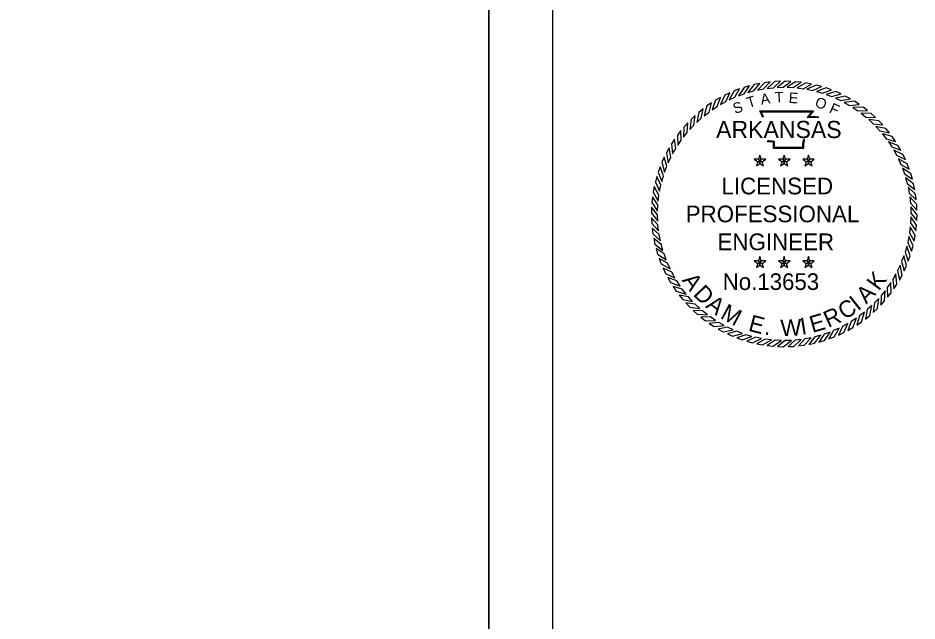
# Model space of a CAD drawing. Extents: x 759422 to 1467355, y 1662254 to 1691786.
# Drawn here: x 1466947.3 to 1467352.3, y 1691241.3 to 1691513 of the extents above; entities that cross this region are included whole.
import ezdxf

# ---------------------------------------------------------------- set-up
doc = ezdxf.new("R2010")
doc.units = 0
doc.layers.add('1', color=7, linetype='Continuous')
doc.layers.add('G-ANNO-STMP-AEW', color=7, linetype='Continuous')

msp = doc.modelspace()

# ---------------------------------------------------------------- linework, layer by layer
at = {"layer": '1'}
msp.add_line((1467159.42, 1690715.04), (1467159.42, 1691757.36), dxfattribs=at)
for points in [[(1467188.26, 1691786.2), (1465488.26, 1691786.2), (1465488.26, 1690686.2), (1467188.26, 1690686.2)], [(1465564.06, 1691229.74), (1465564.06, 1691757.36), (1466748.12, 1691757.36), (1466748.12, 1691707.96), (1466943.92, 1691707.96), (1466943.92, 1691693.36), (1467159.42, 1691693.36), (1467159.42, 1691229.74)], [(1465564.06, 1691757.36), (1466748.12, 1691757.36), (1466748.12, 1691707.96), (1466943.92, 1691707.96), (1466943.92, 1691693.36), (1467159.42, 1691693.36), (1467159.42, 1691229.74), (1465564.06, 1691229.74)]]:
    msp.add_lwpolyline(points, close=True, dxfattribs=at)
at = {"layer": 'G-ANNO-STMP-AEW'}
for points in [[(1467281.44, 1691483.49), (1467278.92, 1691482.96), (1467276.07, 1691479.37), (1467278.75, 1691480.1)], [(1467286.08, 1691484.17), (1467283.53, 1691483.84), (1467280.41, 1691480.49), (1467283.14, 1691481.01)], [(1467290.77, 1691484.49), (1467288.2, 1691484.36), (1467284.82, 1691481.27), (1467287.58, 1691481.57)], [(1467295.47, 1691484.44), (1467292.89, 1691484.51), (1467289.28, 1691481.69), (1467292.06, 1691481.78)], [(1467300.14, 1691484.02), (1467297.59, 1691484.3), (1467293.76, 1691481.77), (1467296.54, 1691481.64)], [(1467304.77, 1691483.24), (1467302.25, 1691483.71), (1467298.24, 1691481.49), (1467300.99, 1691481.14)], [(1467309.33, 1691482.09), (1467306.85, 1691482.76), (1467302.67, 1691480.86), (1467305.4, 1691480.3)], [(1467268.02, 1691479.29), (1467265.69, 1691478.18), (1467263.76, 1691474.03), (1467266.19, 1691475.37)], [(1467272.38, 1691481.04), (1467269.97, 1691480.12), (1467267.72, 1691476.13), (1467270.25, 1691477.27)], [(1467276.86, 1691482.44), (1467274.39, 1691481.72), (1467271.83, 1691477.91), (1467274.44, 1691478.86)], [(1467313.78, 1691480.59), (1467311.36, 1691481.46), (1467307.05, 1691479.89), (1467309.72, 1691479.12)], [(1467318.1, 1691478.75), (1467315.75, 1691479.8), (1467311.33, 1691478.58), (1467313.93, 1691477.6)], [(1467259.78, 1691474.79), (1467257.66, 1691473.34), (1467256.39, 1691468.93), (1467258.59, 1691470.63)], [(1467263.81, 1691477.2), (1467261.58, 1691475.92), (1467259.98, 1691471.62), (1467262.3, 1691473.15)], [(1467322.26, 1691476.57), (1467320, 1691477.81), (1467315.5, 1691476.93), (1467318.02, 1691475.75)], [(1467326.24, 1691474.08), (1467324.09, 1691475.48), (1467319.53, 1691474.96), (1467321.95, 1691473.59)], [(1467255.95, 1691472.07), (1467253.95, 1691470.45), (1467253.04, 1691465.96), (1467255.09, 1691467.83)], [(1467330.01, 1691471.28), (1467327.97, 1691472.85), (1467323.39, 1691472.69), (1467325.69, 1691471.13)], [(1467252.35, 1691469.06), (1467250.48, 1691467.29), (1467249.92, 1691462.74), (1467251.82, 1691464.77)], [(1467333.55, 1691468.19), (1467331.64, 1691469.91), (1467327.06, 1691470.11), (1467329.23, 1691468.38)], [(1467336.83, 1691464.83), (1467335.07, 1691466.7), (1467330.52, 1691467.26), (1467332.54, 1691465.36)], [(1467248.99, 1691465.77), (1467247.27, 1691463.86), (1467247.07, 1691459.28), (1467248.8, 1691461.45)], [(1467339.85, 1691461.23), (1467338.23, 1691463.23), (1467333.74, 1691464.14), (1467335.61, 1691462.09)], [(1467243.1, 1691458.46), (1467241.7, 1691456.31), (1467242.22, 1691451.75), (1467243.59, 1691454.17)], [(1467245.9, 1691462.23), (1467244.33, 1691460.19), (1467244.49, 1691455.61), (1467246.05, 1691457.91)], [(1467342.57, 1691457.4), (1467341.11, 1691459.52), (1467336.71, 1691460.79), (1467338.41, 1691458.59)], [(1467240.61, 1691454.48), (1467239.37, 1691452.23), (1467240.25, 1691447.73), (1467241.43, 1691450.24)], [(1467344.98, 1691453.37), (1467343.7, 1691455.6), (1467339.4, 1691457.2), (1467340.93, 1691454.88)], [(1467238.43, 1691450.32), (1467237.38, 1691447.97), (1467238.6, 1691443.56), (1467239.58, 1691446.16)], [(1467281.54, 1691448.52), (1467282.16, 1691449.36), (1467281.54, 1691451.25), (1467280.93, 1691449.36)], [(1467292.48, 1691448.52), (1467293.09, 1691449.36), (1467292.48, 1691451.25), (1467291.87, 1691449.36)], [(1467303.42, 1691448.52), (1467304.03, 1691449.36), (1467303.42, 1691451.25), (1467302.8, 1691449.36)], [(1467347.06, 1691449.16), (1467345.96, 1691451.49), (1467341.81, 1691453.42), (1467343.15, 1691450.99)], [(1467281.54, 1691448.52), (1467280.93, 1691449.36), (1467278.94, 1691449.36), (1467280.55, 1691448.2)], [(1467281.54, 1691448.52), (1467280.55, 1691448.2), (1467279.93, 1691446.31), (1467281.54, 1691447.47)], [(1467281.54, 1691448.52), (1467282.53, 1691448.2), (1467284.14, 1691449.36), (1467282.16, 1691449.36)], [(1467281.54, 1691448.52), (1467281.54, 1691447.47), (1467283.15, 1691446.31), (1467282.53, 1691448.2)], [(1467292.48, 1691448.52), (1467291.87, 1691449.36), (1467289.88, 1691449.36), (1467291.49, 1691448.2)], [(1467292.48, 1691448.52), (1467291.49, 1691448.2), (1467290.87, 1691446.31), (1467292.48, 1691447.47)], [(1467292.48, 1691448.52), (1467293.47, 1691448.2), (1467295.08, 1691449.36), (1467293.09, 1691449.36)], [(1467292.48, 1691448.52), (1467292.48, 1691447.47), (1467294.09, 1691446.31), (1467293.47, 1691448.2)], [(1467303.42, 1691448.52), (1467302.8, 1691449.36), (1467300.82, 1691449.36), (1467302.42, 1691448.2)], [(1467303.42, 1691448.52), (1467302.42, 1691448.2), (1467301.81, 1691446.31), (1467303.42, 1691447.47)], [(1467303.42, 1691448.52), (1467304.41, 1691448.2), (1467306.02, 1691449.36), (1467304.03, 1691449.36)], [(1467303.42, 1691448.52), (1467303.42, 1691447.47), (1467305.02, 1691446.31), (1467304.41, 1691448.2)], [(1467348.81, 1691444.8), (1467347.9, 1691447.21), (1467343.91, 1691449.46), (1467345.05, 1691446.93)], [(1467236.59, 1691446), (1467235.72, 1691443.58), (1467237.29, 1691439.27), (1467238.06, 1691441.94)], [(1467350.22, 1691440.32), (1467349.49, 1691442.79), (1467345.69, 1691445.35), (1467346.63, 1691442.74)], [(1467235.09, 1691441.55), (1467234.42, 1691439.07), (1467236.32, 1691434.9), (1467236.88, 1691437.62)], [(1467351.27, 1691435.74), (1467350.74, 1691438.26), (1467347.15, 1691441.11), (1467347.88, 1691438.43)], [(1467233.94, 1691437), (1467233.47, 1691434.47), (1467235.69, 1691430.46), (1467236.04, 1691433.22)], [(1467351.95, 1691431.1), (1467351.62, 1691433.65), (1467348.27, 1691436.77), (1467348.79, 1691434.04)], [(1467233.16, 1691432.37), (1467232.88, 1691429.81), (1467235.41, 1691425.99), (1467235.54, 1691428.76)], [(1467352.27, 1691426.41), (1467352.14, 1691428.98), (1467349.04, 1691432.36), (1467349.35, 1691429.6)], [(1467232.74, 1691427.69), (1467232.67, 1691425.12), (1467235.49, 1691421.5), (1467235.4, 1691424.28)], [(1467352.22, 1691421.71), (1467352.29, 1691424.29), (1467349.47, 1691427.9), (1467349.56, 1691425.12)], [(1467232.69, 1691422.99), (1467232.82, 1691420.42), (1467235.91, 1691417.04), (1467235.61, 1691419.8)], [(1467351.8, 1691417.04), (1467352.08, 1691419.59), (1467349.55, 1691423.42), (1467349.42, 1691420.64)], [(1467233.01, 1691418.31), (1467233.34, 1691415.75), (1467236.69, 1691412.63), (1467236.17, 1691415.36)], [(1467351.02, 1691412.41), (1467351.49, 1691414.93), (1467349.27, 1691418.94), (1467348.92, 1691416.19)], [(1467349.87, 1691407.85), (1467350.54, 1691410.33), (1467348.64, 1691414.51), (1467348.08, 1691411.78)], [(1467233.69, 1691413.66), (1467234.22, 1691411.14), (1467237.81, 1691408.29), (1467237.08, 1691410.97)], [(1467348.37, 1691403.4), (1467349.24, 1691405.82), (1467347.67, 1691410.13), (1467346.89, 1691407.46)], [(1467234.74, 1691409.08), (1467235.46, 1691406.61), (1467239.27, 1691404.05), (1467238.32, 1691406.66)], [(1467346.53, 1691399.08), (1467347.58, 1691401.43), (1467346.36, 1691405.85), (1467345.37, 1691403.25)], [(1467236.14, 1691404.6), (1467237.06, 1691402.2), (1467241.05, 1691399.94), (1467239.91, 1691402.47)], [(1467281.54, 1691402.72), (1467280.93, 1691403.56), (1467278.94, 1691403.56), (1467280.55, 1691402.4)], [(1467281.54, 1691402.72), (1467280.55, 1691402.4), (1467279.93, 1691400.51), (1467281.54, 1691401.67)], [(1467281.54, 1691402.72), (1467282.16, 1691403.56), (1467281.54, 1691405.45), (1467280.93, 1691403.56)], [(1467281.54, 1691402.72), (1467282.53, 1691402.4), (1467284.14, 1691403.56), (1467282.16, 1691403.56)], [(1467281.54, 1691402.72), (1467281.54, 1691401.67), (1467283.15, 1691400.51), (1467282.53, 1691402.4)], [(1467292.48, 1691402.72), (1467291.87, 1691403.56), (1467289.88, 1691403.56), (1467291.49, 1691402.4)], [(1467292.48, 1691402.72), (1467291.49, 1691402.4), (1467290.87, 1691400.51), (1467292.48, 1691401.67)], [(1467292.48, 1691402.72), (1467293.09, 1691403.56), (1467292.48, 1691405.45), (1467291.87, 1691403.56)], [(1467292.48, 1691402.72), (1467293.47, 1691402.4), (1467295.08, 1691403.56), (1467293.09, 1691403.56)], [(1467292.48, 1691402.72), (1467292.48, 1691401.67), (1467294.09, 1691400.51), (1467293.47, 1691402.4)], [(1467303.42, 1691402.72), (1467302.8, 1691403.56), (1467300.82, 1691403.56), (1467302.42, 1691402.4)], [(1467303.42, 1691402.72), (1467302.42, 1691402.4), (1467301.81, 1691400.51), (1467303.42, 1691401.67)], [(1467303.42, 1691402.72), (1467304.03, 1691403.56), (1467303.42, 1691405.45), (1467302.8, 1691403.56)], [(1467303.42, 1691402.72), (1467304.41, 1691402.4), (1467306.02, 1691403.56), (1467304.03, 1691403.56)], [(1467303.42, 1691402.72), (1467303.42, 1691401.67), (1467305.02, 1691400.51), (1467304.41, 1691402.4)], [(1467344.35, 1691394.92), (1467345.58, 1691397.18), (1467344.71, 1691401.68), (1467343.53, 1691399.16)], [(1467237.89, 1691400.24), (1467239, 1691397.92), (1467243.15, 1691395.98), (1467241.81, 1691398.41)], [(1467341.86, 1691390.94), (1467343.26, 1691393.09), (1467342.74, 1691397.65), (1467341.37, 1691395.23)], [(1467239.98, 1691396.03), (1467241.26, 1691393.8), (1467245.56, 1691392.2), (1467244.03, 1691394.52)], [(1467339.05, 1691387.17), (1467340.62, 1691389.21), (1467340.46, 1691393.79), (1467338.9, 1691391.49)], [(1467242.39, 1691392), (1467243.84, 1691389.88), (1467248.25, 1691388.62), (1467246.55, 1691390.81)], [(1467335.97, 1691383.63), (1467337.69, 1691385.54), (1467337.89, 1691390.12), (1467336.15, 1691387.95)], [(1467245.11, 1691388.17), (1467246.73, 1691386.17), (1467251.22, 1691385.26), (1467249.35, 1691387.31)], [(1467332.61, 1691380.35), (1467334.48, 1691382.11), (1467335.04, 1691386.66), (1467333.14, 1691384.64)], [(1467248.12, 1691384.57), (1467249.89, 1691382.7), (1467254.44, 1691382.14), (1467252.41, 1691384.04)], [(1467329.01, 1691377.33), (1467331.01, 1691378.95), (1467331.92, 1691383.44), (1467329.87, 1691381.57)], [(1467251.41, 1691381.21), (1467253.32, 1691379.49), (1467257.9, 1691379.29), (1467255.73, 1691381.03)], [(1467254.95, 1691378.13), (1467256.99, 1691376.56), (1467261.57, 1691376.72), (1467259.27, 1691378.28)], [(1467321.15, 1691372.2), (1467323.38, 1691373.48), (1467324.98, 1691377.78), (1467322.66, 1691376.25)], [(1467325.18, 1691374.61), (1467327.3, 1691376.07), (1467328.56, 1691380.47), (1467326.37, 1691378.77)], [(1467258.72, 1691375.32), (1467260.87, 1691373.92), (1467265.43, 1691374.44), (1467263.01, 1691375.81)], [(1467262.7, 1691372.83), (1467264.95, 1691371.6), (1467269.45, 1691372.47), (1467266.94, 1691373.65)], [(1467316.94, 1691370.12), (1467319.26, 1691371.22), (1467321.2, 1691375.37), (1467318.77, 1691374.03)], [(1467266.86, 1691370.65), (1467269.21, 1691369.6), (1467273.62, 1691370.82), (1467271.02, 1691371.81)], [(1467271.18, 1691368.81), (1467273.6, 1691367.94), (1467277.91, 1691369.51), (1467275.24, 1691370.29)], [(1467303.52, 1691365.91), (1467306.04, 1691366.44), (1467308.89, 1691370.03), (1467306.21, 1691369.3)], [(1467308.1, 1691366.96), (1467310.57, 1691367.69), (1467313.13, 1691371.49), (1467310.52, 1691370.55)], [(1467312.58, 1691368.37), (1467314.98, 1691369.28), (1467317.24, 1691373.27), (1467314.71, 1691372.13)], [(1467275.63, 1691367.31), (1467278.11, 1691366.64), (1467282.28, 1691368.54), (1467279.56, 1691369.1)], [(1467280.18, 1691366.16), (1467282.71, 1691365.69), (1467286.72, 1691367.91), (1467283.96, 1691368.26)], [(1467284.81, 1691365.38), (1467287.37, 1691365.1), (1467291.19, 1691367.63), (1467288.42, 1691367.76)], [(1467289.49, 1691364.96), (1467292.06, 1691364.89), (1467295.68, 1691367.71), (1467292.9, 1691367.62)], [(1467294.19, 1691364.91), (1467296.76, 1691365.04), (1467300.14, 1691368.14), (1467297.38, 1691367.83)], [(1467298.87, 1691365.23), (1467301.43, 1691365.56), (1467304.55, 1691368.91), (1467301.82, 1691368.39)]]:
    msp.add_lwpolyline(points, close=True, dxfattribs=at)
for points in [[(1467282.9, 1691468.11), (1467281.5, 1691471.13), (1467305.63, 1691471.15), (1467303.61, 1691468.61), (1467305.25, 1691468.64), (1467306.62, 1691468.65), (1467307.99, 1691468.5)], [(1467283.24, 1691468.27), (1467282.1, 1691470.75), (1467304.84, 1691470.76), (1467302.81, 1691468.22), (1467305.26, 1691468.25), (1467306.6, 1691468.27), (1467307.95, 1691468.12)], [(1467301.83, 1691458), (1467301.42, 1691457.67), (1467301.28, 1691457.17), (1467301.14, 1691455.92), (1467301.14, 1691454.25), (1467287.67, 1691454.25), (1467287.67, 1691456.5), (1467287.67, 1691457), (1467287.13, 1691457.17), (1467285.21, 1691457.17), (1467284.87, 1691457.69)], [(1467301.59, 1691458.3), (1467301.08, 1691457.89), (1467300.9, 1691457.24), (1467300.76, 1691455.94), (1467300.76, 1691454.63), (1467288.06, 1691454.63), (1467288.06, 1691456.5), (1467288.06, 1691457.28), (1467287.18, 1691457.55), (1467285.42, 1691457.55), (1467285.19, 1691457.9)]]:
    msp.add_lwpolyline(points, dxfattribs=at)

# ---------------------------------------------------------------- texts
for s, height, rotation, p in [('A', 4.76, 8.6788, (1467282.16, 1691473.92)), ('T', 4.76, 1.4789, (1467288.31, 1691474.87)), ('E', 4.76, 356.672, (1467294.4, 1691474.72)), ('S', 4.76, 19.7726, (1467270.33, 1691469.7)), ('T', 4.76, 16.9015, (1467276.38, 1691472.41)), ('O', 4.76, 341.2218, (1467305.95, 1691473.09)), ('F', 4.76, 335.3628, (1467312.37, 1691470.58)), ('K', 7.52, 53.8471, (1467335.07, 1691389.71)), ('A', 7.52, 305.982, (1467246.2, 1691394.76)), ('D', 7.52, 314.3022, (1467251.14, 1691388.26)), ('A', 7.52, 45.185, (1467329.43, 1691383.81)), ('A', 7.52, 322.6223, (1467256.71, 1691382.77)), ('C', 7.52, 32.1396, (1467319.67, 1691376.78)), ('I', 7.52, 38.4057, (1467325.64, 1691380.75)), ('M', 7.52, 331.7969, (1467263.28, 1691377.91)), ('R', 7.52, 24.1616, (1467312.3, 1691373.27)), ('E', 7.52, 345.2782, (1467275.94, 1691372.14)), ('W', 7.52, 2.1127, (1467290.89, 1691369.57)), ('I', 7.52, 9.5753, (1467300.34, 1691370.21)), ('E', 7.52, 16.0125, (1467305.13, 1691371.07)), ('.', 7.52, 350.8583, (1467283.25, 1691370.44))]:
    msp.add_text(s, height=height, rotation=rotation, dxfattribs=at).set_placement(p)
for s, height, p in [('ARKANSAS', 7.767, (1467261.78, 1691458.87)), ('LICENSED', 7.52, (1467264.19, 1691433.52)), ('PROFESSIONAL', 7.5196, (1467248.08, 1691420.94)), ('ENGINEER', 7.52, (1467262.4, 1691408.37)), ('No.13653', 7.49, (1467264.77, 1691390.44))]:
    msp.add_text(s, height=height, dxfattribs=at).set_placement(p)

doc.saveas('drawing.dxf')
